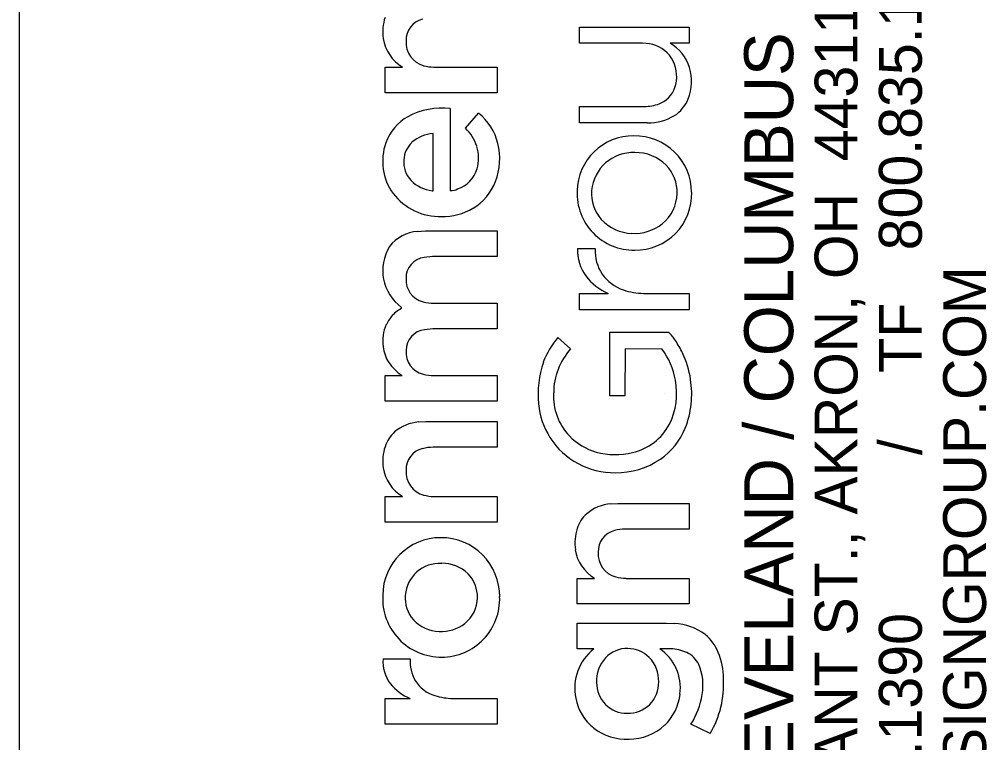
# Model space of a CAD drawing. Extents: x -0.2 to 34, y 0 to 22.
# Drawn here: x 32 to 33.125, y 3.094 to 3.936 of the extents above; entities that cross this region are included whole.
import ezdxf

# ---------------------------------------------------------------- set-up
doc = ezdxf.new("R2010")
doc.units = 0
doc.layers.add('SH_Border', color=7, linetype='Continuous')
doc.layers.add('SH_Data', color=7, linetype='Continuous')

msp = doc.modelspace()

# ---------------------------------------------------------------- linework, layer by layer
at = {"layer": 'SH_Border'}
msp.add_line((32, 0.5), (32, 21.5), dxfattribs=at)
at = {"layer": 'SH_Data'}
for p, q in [((32.6515, 3.908), (32.6515, 3.9267)), ((32.6515, 3.9267), (32.7791, 3.9266)), ((32.7791, 3.9266), (32.7791, 3.908)), ((32.7249, 3.908), (32.6515, 3.908)), ((32.7328, 3.9073), (32.7249, 3.908)), ((32.7791, 3.908), (32.7569, 3.908)), ((32.4254, 3.8503), (32.4254, 3.8802)), ((32.4254, 3.8802), (32.4455, 3.8802)), ((32.4822, 3.8802), (32.5557, 3.8802)), ((32.5557, 3.8802), (32.5557, 3.8504)), ((32.5557, 3.8504), (32.4254, 3.8503)), ((32.5011, 3.8321), (32.5012, 3.7366)), ((32.5188, 3.8093), (32.5342, 3.8266)), ((32.6515, 3.8344), (32.7291, 3.8345)), ((32.6517, 3.8154), (32.6515, 3.8344)), ((32.7307, 3.8154), (32.6517, 3.8154)), ((32.4814, 3.7364), (32.4814, 3.803)), ((32.4802, 3.7363), (32.4814, 3.7364)), ((32.4633, 3.6891), (32.4726, 3.6897)), ((32.4726, 3.6897), (32.5556, 3.6897)), ((32.5556, 3.6897), (32.5557, 3.6598)), ((32.6493, 3.6691), (32.6698, 3.6691)), ((32.4806, 3.6598), (32.471, 3.6588)), ((32.5557, 3.6598), (32.4806, 3.6598)), ((32.6515, 3.598), (32.6515, 3.617)), ((32.6515, 3.617), (32.6848, 3.617)), ((32.726, 3.617), (32.7791, 3.617)), ((32.7791, 3.617), (32.779, 3.598)), ((32.4444, 3.5992), (32.4446, 3.6007)), ((32.4822, 3.6055), (32.5557, 3.6055)), ((32.5557, 3.6055), (32.5557, 3.5757)), ((32.779, 3.598), (32.6515, 3.598)), ((32.4809, 3.5757), (32.4714, 3.5747)), ((32.5557, 3.5757), (32.4809, 3.5757)), ((32.6868, 3.5718), (32.7552, 3.5719)), ((32.6868, 3.4978), (32.6868, 3.5718)), ((32.6264, 3.5655), (32.6411, 3.5524)), ((32.7045, 3.5524), (32.7043, 3.4978)), ((32.7474, 3.5523), (32.7045, 3.5524)), ((32.4254, 3.4915), (32.4254, 3.5214)), ((32.4254, 3.5214), (32.4451, 3.5214)), ((32.4821, 3.5214), (32.5557, 3.5214)), ((32.5557, 3.5214), (32.5557, 3.4916)), ((32.75, 3.5), (32.75, 3.5)), ((32.5557, 3.4916), (32.4254, 3.4915)), ((32.7043, 3.4978), (32.6868, 3.4978)), ((32.4644, 3.4674), (32.4729, 3.4678)), ((32.4729, 3.4678), (32.5557, 3.4678)), ((32.5557, 3.4678), (32.5557, 3.438)), ((32.5557, 3.438), (32.4814, 3.438)), ((32.4254, 3.3509), (32.4254, 3.3807)), ((32.4254, 3.3807), (32.4455, 3.3807)), ((32.4822, 3.3807), (32.5557, 3.3807)), ((32.5557, 3.3807), (32.5557, 3.351)), ((32.6878, 3.3722), (32.6963, 3.3727)), ((32.6963, 3.3727), (32.7792, 3.3727)), ((32.7792, 3.3727), (32.7792, 3.3429)), ((32.5557, 3.351), (32.4254, 3.3509)), ((32.7792, 3.3429), (32.7048, 3.3428)), ((32.6489, 3.2557), (32.6489, 3.2855)), ((32.6489, 3.2855), (32.669, 3.2855)), ((32.7057, 3.2855), (32.7791, 3.2855)), ((32.7791, 3.2855), (32.7792, 3.2558)), ((32.7792, 3.2558), (32.6489, 3.2557)), ((32.6489, 3.2034), (32.6489, 3.2332)), ((32.6489, 3.2332), (32.7524, 3.2332)), ((32.7524, 3.2332), (32.7619, 3.2329)), ((32.6684, 3.2034), (32.6489, 3.2034)), ((32.7576, 3.2036), (32.7449, 3.2036)), ((32.423, 3.1919), (32.4545, 3.1919)), ((32.4254, 3.1159), (32.4254, 3.1458)), ((32.4254, 3.1458), (32.4547, 3.1458)), ((32.5041, 3.1458), (32.5557, 3.1457)), ((32.5557, 3.1457), (32.5556, 3.1159)), ((32.5556, 3.1159), (32.4254, 3.1159)), ((32.8036, 3.1049), (32.7812, 3.116))]:
    msp.add_line(p, q, dxfattribs=at)
for points in [[(32.7328, 3.9073), (32.7249, 3.908), (32.6515, 3.908), (32.6515, 3.9267), (32.7791, 3.9266), (32.7791, 3.908), (32.7569, 3.908)], [(32.4254, 3.8503), (32.4254, 3.8802), (32.4455, 3.8802)], [(32.4822, 3.8802), (32.5557, 3.8802), (32.5557, 3.8504), (32.4254, 3.8503)], [(32.5011, 3.8321), (32.5012, 3.7366)], [(32.5188, 3.8093), (32.5342, 3.8266)], [(32.7307, 3.8154), (32.6517, 3.8154), (32.6515, 3.8344), (32.7291, 3.8345)], [(32.4802, 3.7363), (32.4814, 3.7364), (32.4814, 3.803)], [(32.4633, 3.6891), (32.4726, 3.6897), (32.5556, 3.6897), (32.5557, 3.6598), (32.4806, 3.6598), (32.471, 3.6588)], [(32.6493, 3.6691), (32.6698, 3.6691)], [(32.6515, 3.598), (32.6515, 3.617), (32.6848, 3.617)], [(32.726, 3.617), (32.7791, 3.617), (32.779, 3.598), (32.6515, 3.598)], [(32.4444, 3.5992), (32.4446, 3.6007)], [(32.4822, 3.6055), (32.5557, 3.6055), (32.5557, 3.5757), (32.4809, 3.5757), (32.4714, 3.5747)], [(32.7474, 3.5523), (32.7045, 3.5524), (32.7043, 3.4978), (32.6868, 3.4978), (32.6868, 3.5718), (32.7552, 3.5719)], [(32.6264, 3.5655), (32.6411, 3.5524)], [(32.4254, 3.4915), (32.4254, 3.5214), (32.4451, 3.5214)], [(32.4821, 3.5214), (32.5557, 3.5214), (32.5557, 3.4916), (32.4254, 3.4915)], [(32.4644, 3.4674), (32.4729, 3.4678), (32.5557, 3.4678), (32.5557, 3.438), (32.4814, 3.438)], [(32.4254, 3.3509), (32.4254, 3.3807), (32.4455, 3.3807)], [(32.4822, 3.3807), (32.5557, 3.3807), (32.5557, 3.351), (32.4254, 3.3509)], [(32.6878, 3.3722), (32.6963, 3.3727), (32.7792, 3.3727), (32.7792, 3.3429), (32.7048, 3.3428)], [(32.6489, 3.2557), (32.6489, 3.2855), (32.669, 3.2855)], [(32.7057, 3.2855), (32.7791, 3.2855), (32.7792, 3.2558), (32.6489, 3.2557)], [(32.6684, 3.2034), (32.6489, 3.2034), (32.6489, 3.2332), (32.7524, 3.2332), (32.7619, 3.2329)], [(32.7576, 3.2036), (32.7449, 3.2036)], [(32.423, 3.1919), (32.4545, 3.1919)], [(32.4254, 3.1159), (32.4254, 3.1458), (32.4547, 3.1458)], [(32.5041, 3.1458), (32.5557, 3.1457), (32.5556, 3.1159), (32.4254, 3.1159)], [(32.8036, 3.1049), (32.7812, 3.116)]]:
    msp.add_lwpolyline(points, dxfattribs=at)
for centre, radius, start, end in [((32.4787, 3.9211), 0.056, 162.274, 187.7917), ((32.4787, 3.9211), 0.056, 162.274, 187.7917), ((32.4748, 3.9116), 0.025, 103.6868, 182.214), ((32.4748, 3.9116), 0.025, 103.6868, 182.214), ((32.4703, 3.9209), 0.0476, 188.9646, 238.6987), ((32.4703, 3.9209), 0.0476, 188.9646, 238.6987), ((32.4774, 3.9085), 0.0276, 175.5844, 255.1382), ((32.4774, 3.9085), 0.0276, 175.5844, 255.1382), ((32.7271, 3.87), 0.0377, 33.5008, 81.3295), ((32.7271, 3.87), 0.0377, 33.5008, 81.3295), ((32.7324, 3.8648), 0.0496, 17.6221, 60.3897), ((32.7324, 3.8648), 0.0496, 17.6221, 60.3897), ((32.4818, 3.9224), 0.0421, 254.0891, 270.5284), ((32.4818, 3.9224), 0.0421, 254.0891, 270.5284), ((32.7241, 3.8695), 0.0405, 346.5618, 31.7539), ((32.7241, 3.8695), 0.0405, 346.5618, 31.7539), ((32.7234, 3.8641), 0.0584, 339.162, 15.6148), ((32.7234, 3.8641), 0.0584, 339.162, 15.6148), ((32.7337, 3.8662), 0.0304, 294.6321, 348.4863), ((32.7337, 3.8662), 0.0304, 294.6321, 348.4863), ((32.7275, 3.8808), 0.0463, 271.952, 294.0894), ((32.7275, 3.8808), 0.0463, 271.952, 294.0894), ((32.739, 3.859), 0.042, 303.1039, 338.1561), ((32.739, 3.859), 0.042, 303.1039, 338.1561), ((32.4918, 3.7487), 0.0839, 83.6212, 118.2845), ((32.4918, 3.7487), 0.0839, 83.6212, 118.2845), ((32.494, 3.7763), 0.0644, 13.5328, 51.3627), ((32.494, 3.7763), 0.0644, 13.5328, 51.3627), ((32.4789, 3.7737), 0.0558, 118.8294, 160.6224), ((32.4789, 3.7737), 0.0558, 118.8294, 160.6224), ((32.7321, 3.8726), 0.0571, 268.627, 301.4778), ((32.7321, 3.8726), 0.0571, 268.627, 301.4778), ((32.4844, 3.7607), 0.0424, 94.0131, 130.8806), ((32.4844, 3.7607), 0.0424, 94.0131, 130.8806), ((32.4803, 3.7702), 0.0549, 19.0387, 45.4432), ((32.4803, 3.7702), 0.0549, 19.0387, 45.4432), ((32.487, 3.7707), 0.0644, 160.5214, 215.7815), ((32.487, 3.7707), 0.0644, 160.5214, 215.7815), ((32.477, 3.7709), 0.0298, 132.9855, 177.1802), ((32.477, 3.7709), 0.0298, 132.9855, 177.1802), ((32.7143, 3.7348), 0.0655, 89.4821, 178.7775), ((32.7143, 3.7348), 0.0655, 89.4821, 178.7775), ((32.7158, 3.7341), 0.0662, 0.4227, 90.7613), ((32.7158, 3.7341), 0.0662, 0.4227, 90.7613), ((32.4872, 3.7743), 0.047, 344.6072, 17.0067), ((32.4872, 3.7743), 0.047, 344.6072, 17.0067), ((32.4829, 3.7738), 0.0758, 339.3543, 13.3771), ((32.4829, 3.7738), 0.0758, 339.3543, 13.3771), ((32.714, 3.7324), 0.0485, 87.6883, 175.017), ((32.714, 3.7324), 0.0485, 87.6883, 175.017), ((32.7166, 3.7304), 0.0505, 44.912, 90.7591), ((32.7166, 3.7304), 0.0505, 44.912, 90.7591), ((32.4782, 3.7697), 0.0311, 175.0014, 223.2876), ((32.4782, 3.7697), 0.0311, 175.0014, 223.2876), ((32.499, 3.7718), 0.035, 288.0108, 343.5536), ((32.499, 3.7718), 0.035, 288.0108, 343.5536), ((32.7196, 3.7345), 0.0455, 358.3228, 43.8349), ((32.7196, 3.7345), 0.0455, 358.3228, 43.8349), ((32.4855, 3.7783), 0.0423, 225.0645, 262.797), ((32.4855, 3.7783), 0.0423, 225.0645, 262.797), ((32.4955, 3.7698), 0.0626, 300.9439, 338.7322), ((32.4955, 3.7698), 0.0626, 300.9439, 338.7322), ((32.5013, 3.7568), 0.0202, 269.7004, 294.8729), ((32.5013, 3.7568), 0.0202, 269.7004, 294.8729), ((32.7148, 3.7334), 0.0661, 177.5373, 270.9452), ((32.7148, 3.7334), 0.0661, 177.5373, 270.9452), ((32.7108, 3.7331), 0.0453, 175.5147, 221.4205), ((32.7108, 3.7331), 0.0453, 175.5147, 221.4205), ((32.4891, 3.7752), 0.0687, 217.7434, 271.6561), ((32.4891, 3.7752), 0.0687, 217.7434, 271.6561), ((32.7167, 3.7327), 0.0654, 269.3083, 1.6791), ((32.7167, 3.7327), 0.0654, 269.3083, 1.6791), ((32.7193, 3.7337), 0.0457, 308.9038, 359.3095), ((32.7193, 3.7337), 0.0457, 308.9038, 359.3095), ((32.492, 3.777), 0.0706, 269.2053, 300.3357), ((32.492, 3.777), 0.0706, 269.2053, 300.3357), ((32.714, 3.7373), 0.0505, 222.6626, 268.3733), ((32.714, 3.7373), 0.0505, 222.6626, 268.3733), ((32.7157, 3.7386), 0.0518, 266.5531, 308.6725), ((32.7157, 3.7386), 0.0518, 266.5531, 308.6725), ((32.4664, 3.644), 0.0452, 93.9112, 142.3072), ((32.4664, 3.644), 0.0452, 93.9112, 142.3072), ((32.4759, 3.6437), 0.0532, 148.2879, 233.9556), ((32.4759, 3.6437), 0.0532, 148.2879, 233.9556), ((32.6988, 3.6666), 0.0495, 177.1621, 216.2802), ((32.6988, 3.6666), 0.0495, 177.1621, 216.2802), ((32.7173, 3.6664), 0.0476, 176.7699, 252.1504), ((32.7173, 3.6664), 0.0476, 176.7699, 252.1504), ((32.4738, 3.635), 0.024, 96.7576, 181.6251), ((32.4738, 3.635), 0.024, 96.7576, 181.6251), ((32.4758, 3.6324), 0.026, 175.8157, 256.1672), ((32.4758, 3.6324), 0.026, 175.8157, 256.1672), ((32.7098, 3.6755), 0.0637, 216.9153, 246.8862), ((32.7098, 3.6755), 0.0637, 216.9153, 246.8862), ((32.7269, 3.6917), 0.0747, 251.1388, 269.3469), ((32.7269, 3.6917), 0.0747, 251.1388, 269.3469), ((32.4817, 3.6505), 0.045, 254.3463, 270.6103), ((32.4817, 3.6505), 0.045, 254.3463, 270.6103), ((32.4619, 3.5645), 0.0387, 139.5245, 154.847), ((32.4619, 3.5645), 0.0387, 139.5245, 154.847), ((32.4638, 3.5627), 0.0414, 117.9163, 139.243), ((32.4638, 3.5627), 0.0414, 117.9163, 139.243), ((32.4714, 3.5612), 0.0488, 156.0638, 187.3493), ((32.4714, 3.5612), 0.0488, 156.0638, 187.3493), ((32.4742, 3.5506), 0.0243, 96.5532, 179.949), ((32.4742, 3.5506), 0.0243, 96.5532, 179.949), ((32.725, 3.5394), 0.0444, 30.9891, 47.161), ((32.725, 3.5394), 0.0444, 30.9891, 47.161), ((32.7016, 3.5019), 0.0986, 139.7948, 159.137), ((32.7016, 3.5019), 0.0986, 139.7948, 159.137), ((32.6709, 3.5002), 0.1111, 25.3031, 33.9618), ((32.6709, 3.5002), 0.1111, 25.3031, 33.9618), ((32.4646, 3.5597), 0.0418, 186.5579, 213.3885), ((32.4646, 3.5597), 0.0418, 186.5579, 213.3885), ((32.4761, 3.5486), 0.0263, 175.722, 255.7863), ((32.4761, 3.5486), 0.0263, 175.722, 255.7863), ((32.699, 3.5008), 0.0775, 138.258, 179.7006), ((32.699, 3.5008), 0.0775, 138.258, 179.7006), ((32.6789, 3.501), 0.0856, 10.0751, 36.8319), ((32.6789, 3.501), 0.0856, 10.0751, 36.8319), ((32.6704, 3.4999), 0.1117, 8.8034, 25.3348), ((32.6704, 3.4999), 0.1117, 8.8034, 25.3348), ((32.4789, 3.5708), 0.0598, 214.7043, 235.6872), ((32.4789, 3.5708), 0.0598, 214.7043, 235.6872), ((32.7187, 3.4997), 0.1154, 161.1438, 185.6281), ((32.7187, 3.4997), 0.1154, 161.1438, 185.6281), ((32.4819, 3.5652), 0.0438, 253.6672, 270.1498), ((32.4819, 3.5652), 0.0438, 253.6672, 270.1498), ((32.6842, 3.5006), 0.0804, 333.4669, 11.0367), ((32.6842, 3.5006), 0.0804, 333.4669, 11.0367), ((32.6756, 3.4998), 0.1065, 338.2887, 9.2855), ((32.6756, 3.4998), 0.1065, 338.2887, 9.2855), ((32.6881, 3.4973), 0.0668, 176.6658, 223.6912), ((32.6881, 3.4973), 0.0668, 176.6658, 223.6912), ((32.6934, 3.497), 0.0899, 185.5077, 212.0129), ((32.6934, 3.497), 0.0899, 185.5077, 212.0129), ((32.4687, 3.4177), 0.0499, 94.9706, 130.2248), ((32.4687, 3.4177), 0.0499, 94.9706, 130.2248), ((32.4635, 3.426), 0.0402, 132.2238, 161.6823), ((32.4635, 3.426), 0.0402, 132.2238, 161.6823), ((32.6987, 3.4955), 0.0652, 282.8815, 331.8147), ((32.6987, 3.4955), 0.0652, 282.8815, 331.8147), ((32.6984, 3.4917), 0.0824, 305.0306, 337.6757), ((32.6984, 3.4917), 0.0824, 305.0306, 337.6757), ((32.6921, 3.4975), 0.0891, 212.7022, 270.714), ((32.6921, 3.4975), 0.0891, 212.7022, 270.714), ((32.6905, 3.5001), 0.0704, 224.0215, 253.88), ((32.6905, 3.5001), 0.0704, 224.0215, 253.88), ((32.4787, 3.4216), 0.056, 162.274, 187.7917), ((32.4787, 3.4216), 0.056, 162.274, 187.7917), ((32.4748, 3.4121), 0.025, 103.6868, 182.214), ((32.4748, 3.4121), 0.025, 103.6868, 182.214), ((32.4811, 3.392), 0.046, 89.6051, 105.3303), ((32.4811, 3.392), 0.046, 89.6051, 105.3303), ((32.6932, 3.5125), 0.0831, 254.4535, 283.9512), ((32.6932, 3.5125), 0.0831, 254.4535, 283.9512), ((32.6943, 3.4998), 0.0914, 269.3273, 304.1963), ((32.6943, 3.4998), 0.0914, 269.3273, 304.1963), ((32.4703, 3.4214), 0.0476, 188.9646, 238.6987), ((32.4703, 3.4214), 0.0476, 188.9646, 238.6987), ((32.4774, 3.409), 0.0276, 175.5844, 255.1382), ((32.4774, 3.409), 0.0276, 175.5844, 255.1382), ((32.4818, 3.4229), 0.0421, 254.0891, 270.5284), ((32.4818, 3.4229), 0.0421, 254.0891, 270.5284), ((32.6922, 3.3225), 0.0499, 94.9706, 130.2248), ((32.6922, 3.3225), 0.0499, 94.9706, 130.2248), ((32.6869, 3.3309), 0.0402, 132.2238, 161.6823), ((32.6869, 3.3309), 0.0402, 132.2238, 161.6823), ((32.7022, 3.3264), 0.056, 162.274, 187.7917), ((32.7022, 3.3264), 0.056, 162.274, 187.7917), ((32.7045, 3.2968), 0.046, 89.6051, 105.3303), ((32.7045, 3.2968), 0.046, 89.6051, 105.3303), ((32.4901, 3.2654), 0.0674, 89.8476, 179.6405), ((32.4901, 3.2654), 0.0674, 89.8476, 179.6405), ((32.4906, 3.2647), 0.0681, 359.5401, 90.2114), ((32.4906, 3.2647), 0.0681, 359.5401, 90.2114), ((32.6983, 3.3169), 0.025, 103.6868, 182.214), ((32.6983, 3.3169), 0.025, 103.6868, 182.214), ((32.6937, 3.3262), 0.0476, 188.9646, 238.6987), ((32.6937, 3.3262), 0.0476, 188.9646, 238.6987), ((32.7008, 3.3138), 0.0276, 175.5844, 255.1382), ((32.7008, 3.3138), 0.0276, 175.5844, 255.1382), ((32.4892, 3.2626), 0.0404, 87.0481, 175.5726), ((32.4892, 3.2626), 0.0404, 87.0481, 175.5726), ((32.492, 3.26), 0.043, 45.8426, 90.9801), ((32.492, 3.26), 0.043, 45.8426, 90.9801), ((32.4946, 3.2642), 0.0382, 357.8857, 44.159), ((32.4946, 3.2642), 0.0382, 357.8857, 44.159), ((32.7053, 3.3277), 0.0421, 254.0891, 270.5284), ((32.7053, 3.3277), 0.0421, 254.0891, 270.5284), ((32.4908, 3.2621), 0.0682, 176.8344, 270.4038), ((32.4908, 3.2621), 0.0682, 176.8344, 270.4038), ((32.4873, 3.2625), 0.0385, 175.1538, 221.1471), ((32.4873, 3.2625), 0.0385, 175.1538, 221.1471), ((32.4912, 3.2614), 0.0675, 270.0624, 2.3776), ((32.4912, 3.2614), 0.0675, 270.0624, 2.3776), ((32.4945, 3.2632), 0.0383, 308.2894, 359.4347), ((32.4945, 3.2632), 0.0383, 308.2894, 359.4347), ((32.4892, 3.2661), 0.0423, 223.0999, 268.8089), ((32.4892, 3.2661), 0.0423, 223.0999, 268.8089), ((32.491, 3.2679), 0.0442, 266.5651, 308.0608), ((32.491, 3.2679), 0.0442, 266.5651, 308.0608), ((32.7591, 3.1679), 0.065, 53.4034, 87.4906), ((32.7591, 3.1679), 0.065, 53.4034, 87.4906), ((32.7652, 3.1804), 0.0514, 21.6075, 50.5577), ((32.7652, 3.1804), 0.0514, 21.6075, 50.5577), ((32.7029, 3.1581), 0.0569, 127.3748, 192.2247), ((32.7029, 3.1581), 0.0569, 127.3748, 192.2247), ((32.7069, 3.1693), 0.0346, 88.473, 136.4256), ((32.7069, 3.1693), 0.0346, 88.473, 136.4256), ((32.7081, 3.1696), 0.0342, 44.2719, 90.4762), ((32.7081, 3.1696), 0.0342, 44.2719, 90.4762), ((32.7142, 3.1583), 0.0547, 352.1125, 55.923), ((32.7142, 3.1583), 0.0547, 352.1125, 55.923), ((32.7567, 3.1572), 0.0463, 65.0169, 88.8011), ((32.7567, 3.1572), 0.0463, 65.0169, 88.8011), ((32.7626, 3.1716), 0.0309, 26.2681, 63.803), ((32.7626, 3.1716), 0.0309, 26.2681, 63.803), ((32.7307, 3.1671), 0.0884, 1.1514, 21.3627), ((32.7307, 3.1671), 0.0884, 1.1514, 21.3627), ((32.4662, 3.1888), 0.0433, 175.8731, 216.3475), ((32.4662, 3.1888), 0.0433, 175.8731, 216.3475), ((32.5009, 3.1895), 0.0464, 176.9688, 209.6064), ((32.5009, 3.1895), 0.0464, 176.9688, 209.6064), ((32.7114, 3.166), 0.0401, 137.4674, 182.3324), ((32.7114, 3.166), 0.0401, 137.4674, 182.3324), ((32.7037, 3.166), 0.04, 358.5714, 43.5376), ((32.7037, 3.166), 0.04, 358.5714, 43.5376), ((32.7357, 3.1615), 0.0595, 349.3073, 23.4307), ((32.7357, 3.1615), 0.0595, 349.3073, 23.4307), ((32.4747, 3.1972), 0.0551, 218.0981, 248.7907), ((32.4747, 3.1972), 0.0551, 218.0981, 248.7907), ((32.4951, 3.1881), 0.0408, 211.9447, 253.2028), ((32.4951, 3.1881), 0.0408, 211.9447, 253.2028), ((32.7065, 3.1637), 0.0351, 178.8821, 271.0837), ((32.7065, 3.1637), 0.0351, 178.8821, 271.0837), ((32.7082, 3.164), 0.0355, 268.2788, 1.5502), ((32.7082, 3.164), 0.0355, 268.2788, 1.5502), ((32.7054, 3.1624), 0.1138, 329.6388, 3.26), ((32.7054, 3.1624), 0.1138, 329.6388, 3.26), ((32.7099, 3.1571), 0.0589, 313.742, 353.8554), ((32.7099, 3.1571), 0.0589, 313.742, 353.8554), ((32.7074, 3.1633), 0.0877, 327.3149, 351.5748), ((32.7074, 3.1633), 0.0877, 327.3149, 351.5748), ((32.5047, 3.2165), 0.0707, 252.4655, 269.573), ((32.5047, 3.2165), 0.0707, 252.4655, 269.573), ((32.7046, 3.157), 0.0584, 190.7518, 231.2892), ((32.7046, 3.157), 0.0584, 190.7518, 231.2892), ((32.7063, 3.1611), 0.0627, 232.4606, 272.5902), ((32.7063, 3.1611), 0.0627, 232.4606, 272.5902), ((32.7095, 3.159), 0.0605, 269.6361, 312.7088), ((32.7095, 3.159), 0.0605, 269.6361, 312.7088)]:
    msp.add_arc(centre, radius, start, end, dxfattribs=at)

# ---------------------------------------------------------------- texts
for s, height, p in [('800.835.1390', 0.049846, (33.0497, 3.6671)), ('450 GRANT ST., AKRON, OH  44311', 0.049846, (32.9749, 2.8374)), ('AKRON / CLEVELAND / COLUMBUS', 0.056969, (32.9001, 2.638)), ('ENVDESIGNGROUP.COM', 0.049846, (33.1244, 2.8374)), ('TF', 0.04985, (33.0497, 3.5246)), ('/  ', 0.04985, (33.0497, 3.4288)), ('330.375.1390', 0.049846, (33.0497, 2.8374))]:
    msp.add_text(s, height=height, rotation=90, dxfattribs=at).set_placement(p)

doc.saveas('drawing.dxf')
